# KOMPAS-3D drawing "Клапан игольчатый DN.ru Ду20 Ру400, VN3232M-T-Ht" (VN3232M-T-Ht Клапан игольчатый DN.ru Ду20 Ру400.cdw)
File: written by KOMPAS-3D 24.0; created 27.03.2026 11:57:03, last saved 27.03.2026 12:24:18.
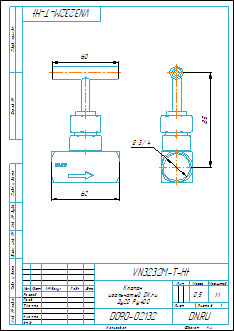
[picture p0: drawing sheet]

Document properties: Автор: Илья; Форматы листов документа: A4; Полное имя файла: VN3232M-T-Ht Клапан игольчатый DN.ru Ду20 Ру400.m3d; Масса: 0.5; Наименование: Клапан игольчатый DN.ru Ду20 Ру400; Количество листов документа: 1; Примечание: D090-02132

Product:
- Body: Body9  | qty 1
    Масса: 0.433192
- Part/product: Клапан игольчатый DN.ru Ду20 Ру400  | designation VN3232M-T-Ht
    Масса: 0.5
    Раздел спецификации: Прочие изделия
    Примечание: D090-02132

Views: Вид 1, Слева
Referenced files in D:\Обмен\Заказы с фриланса\DN.ru\VNxxM-T-Ht Клапан игольчатый DN.ru Ду8-50 Ру400\VN3232M-T-Ht Клапан игольчатый DN.ru Ду8-50 Ру400\DN8\: VN3232M-T-Ht Клапан игольчатый DN.ru Ду8 Ру400.m3d, VN3232M-T-Ht Клапан игольчатый DN.ru Ду8 Ру400.cdw
Referenced files in D:\Обмен\Заказы с фриланса\DN.ru\VNxxM-T-Ht Клапан игольчатый DN.ru Ду8-50 Ру400\VN3232M-T-Ht Клапан игольчатый DN.ru Ду8-50 Ру400\DN20\: VN3232M-T-Ht Клапан игольчатый DN.ru Ду20 Ру400.m3d
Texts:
  VN3232M-T-Ht
  Клапан
  игольчатый DN.ru
  Ду20 Ру400
  Body9
  Клапан игольчатый DN.ru Ду20 Ру400
  VN3232M-T-Ht Клапан игольчатый DN.ru Ду20 Ру400
Dimensions and other numbers on the sheet: 0; 3; 2; 4; 60; 62; 1:1; 1; 0,5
